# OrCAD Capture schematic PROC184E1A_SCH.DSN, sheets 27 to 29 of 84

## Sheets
27 26. SOC DIGITAL POWER 3: size C; title: SOC DIGITAL POWER 3; company: TEXAS INSTRUMENTS INCORPORATED; note: PROC184_SCH
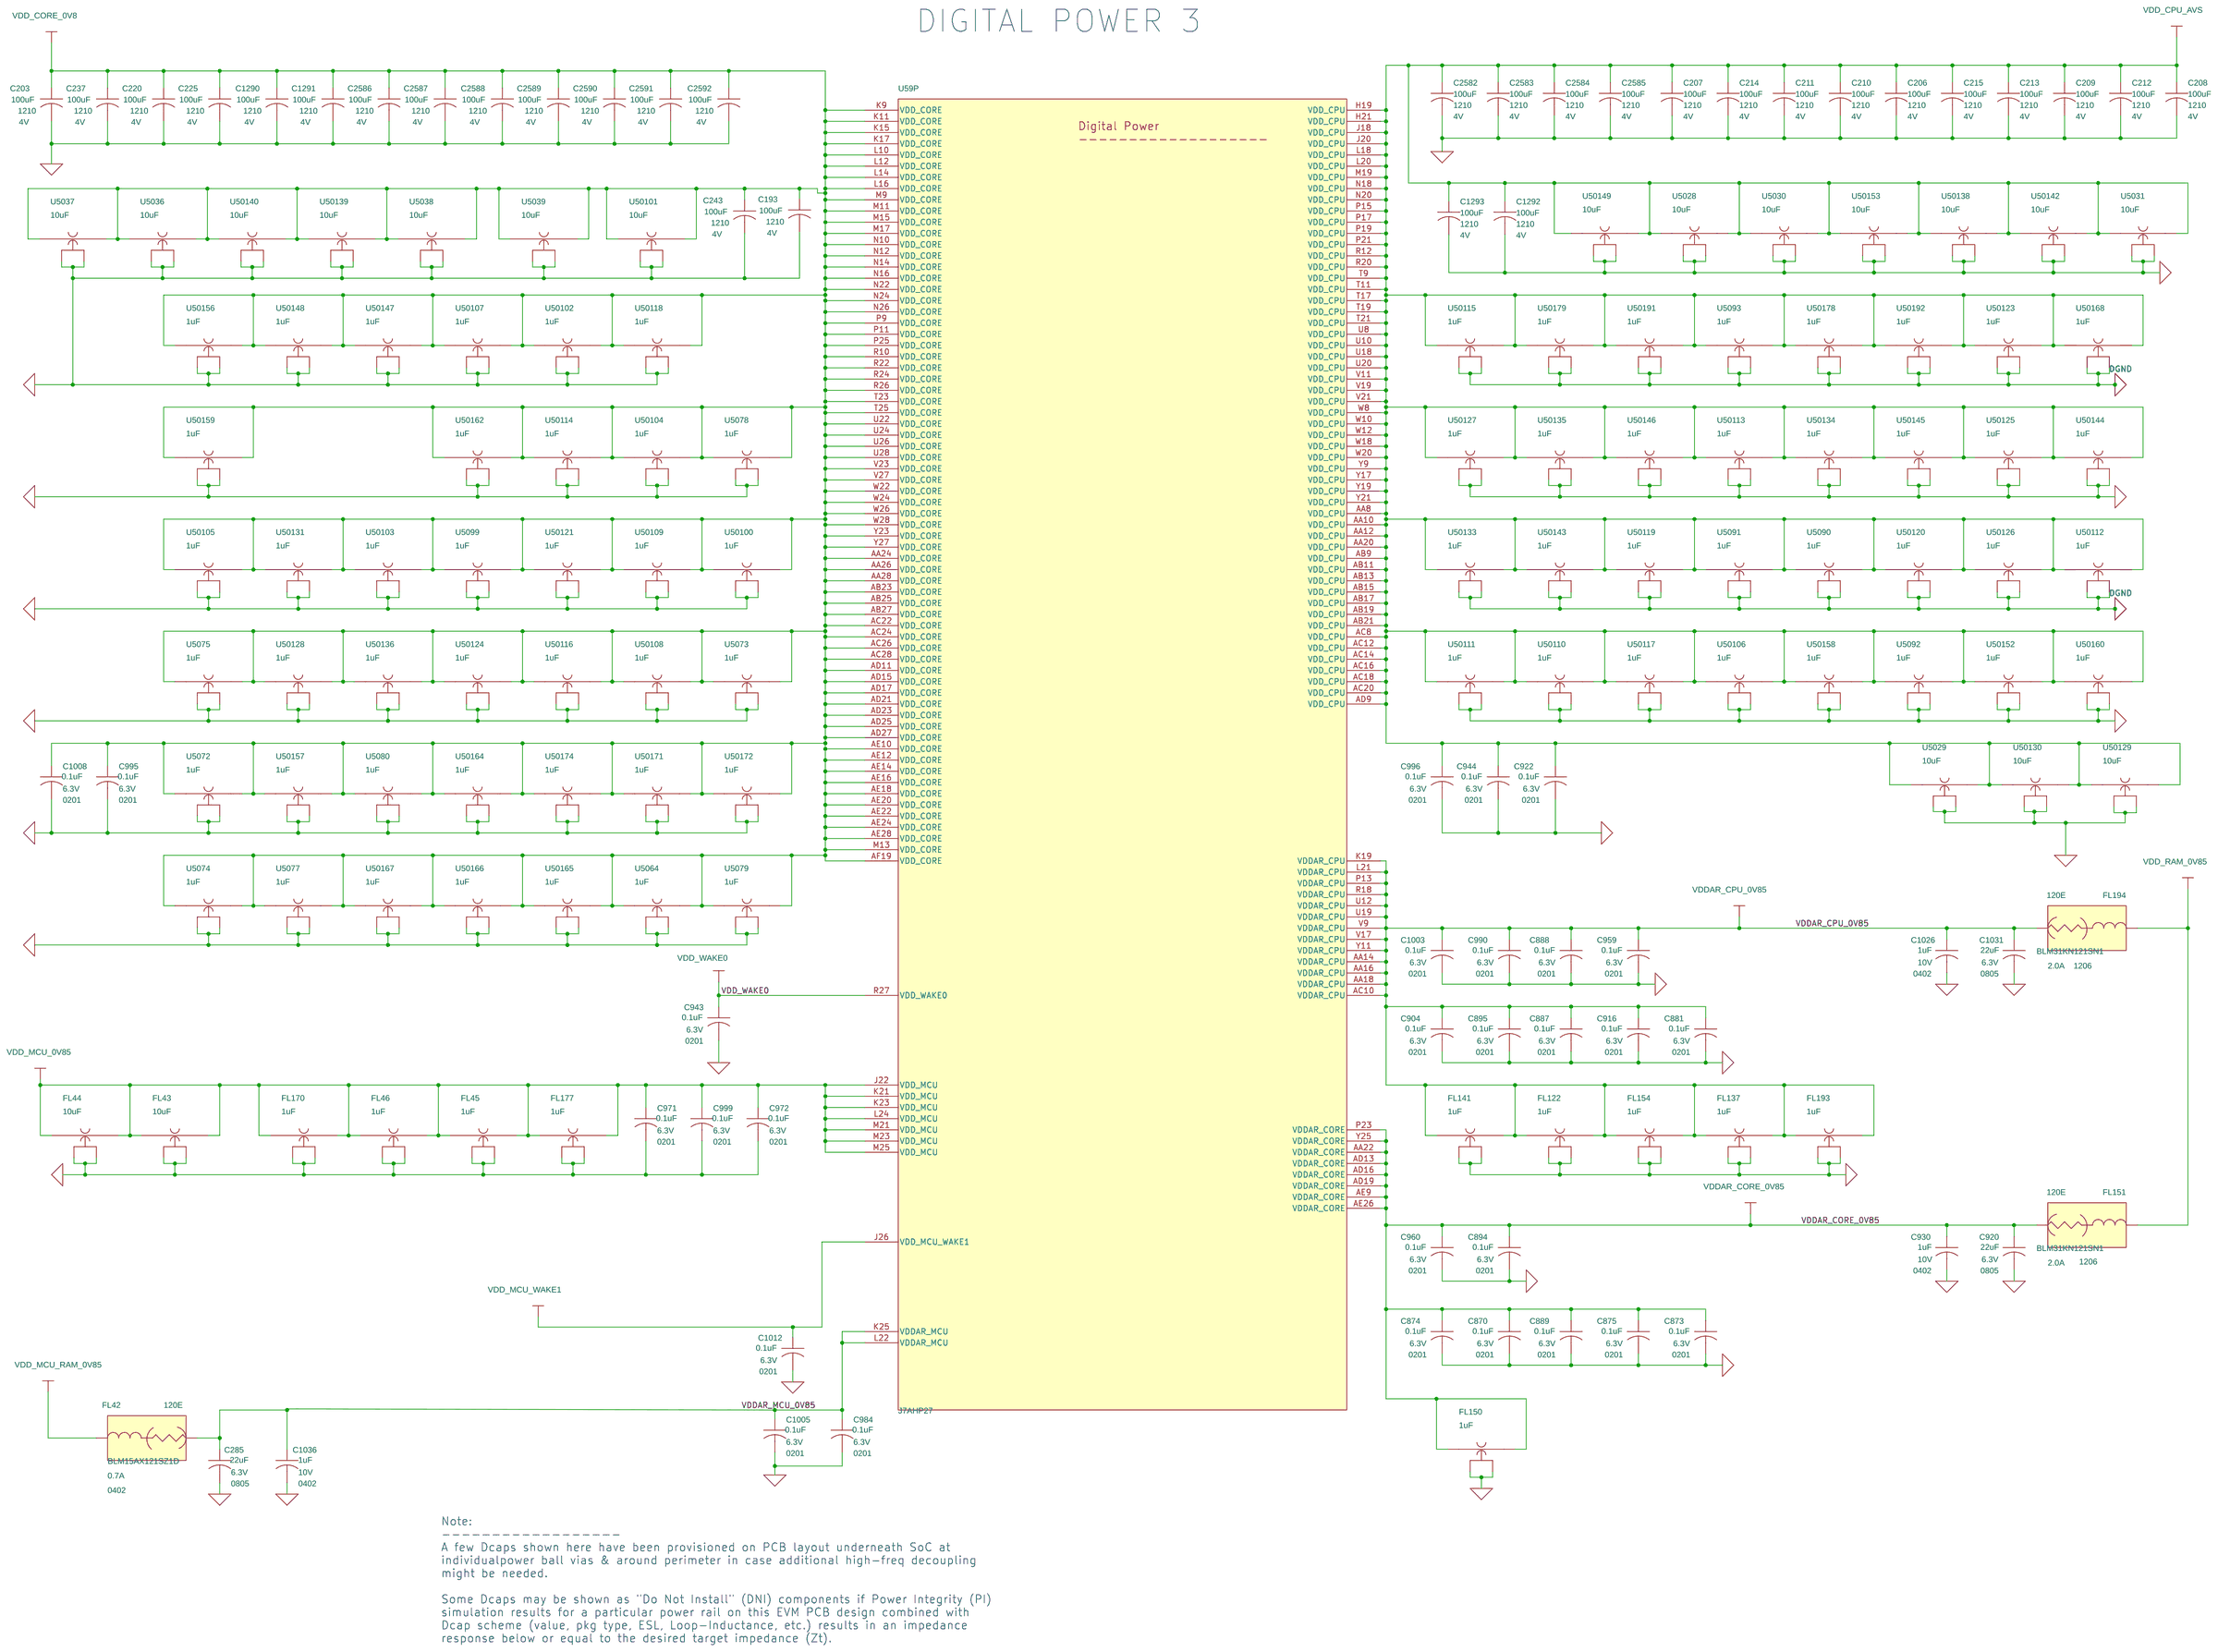
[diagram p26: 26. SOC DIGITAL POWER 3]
28 27. SOC GND & KELVIN SENSING: size C; title: SOC GROUND; company: TEXAS INSTRUMENTS INCORPORATED; note: PROC184_SCH
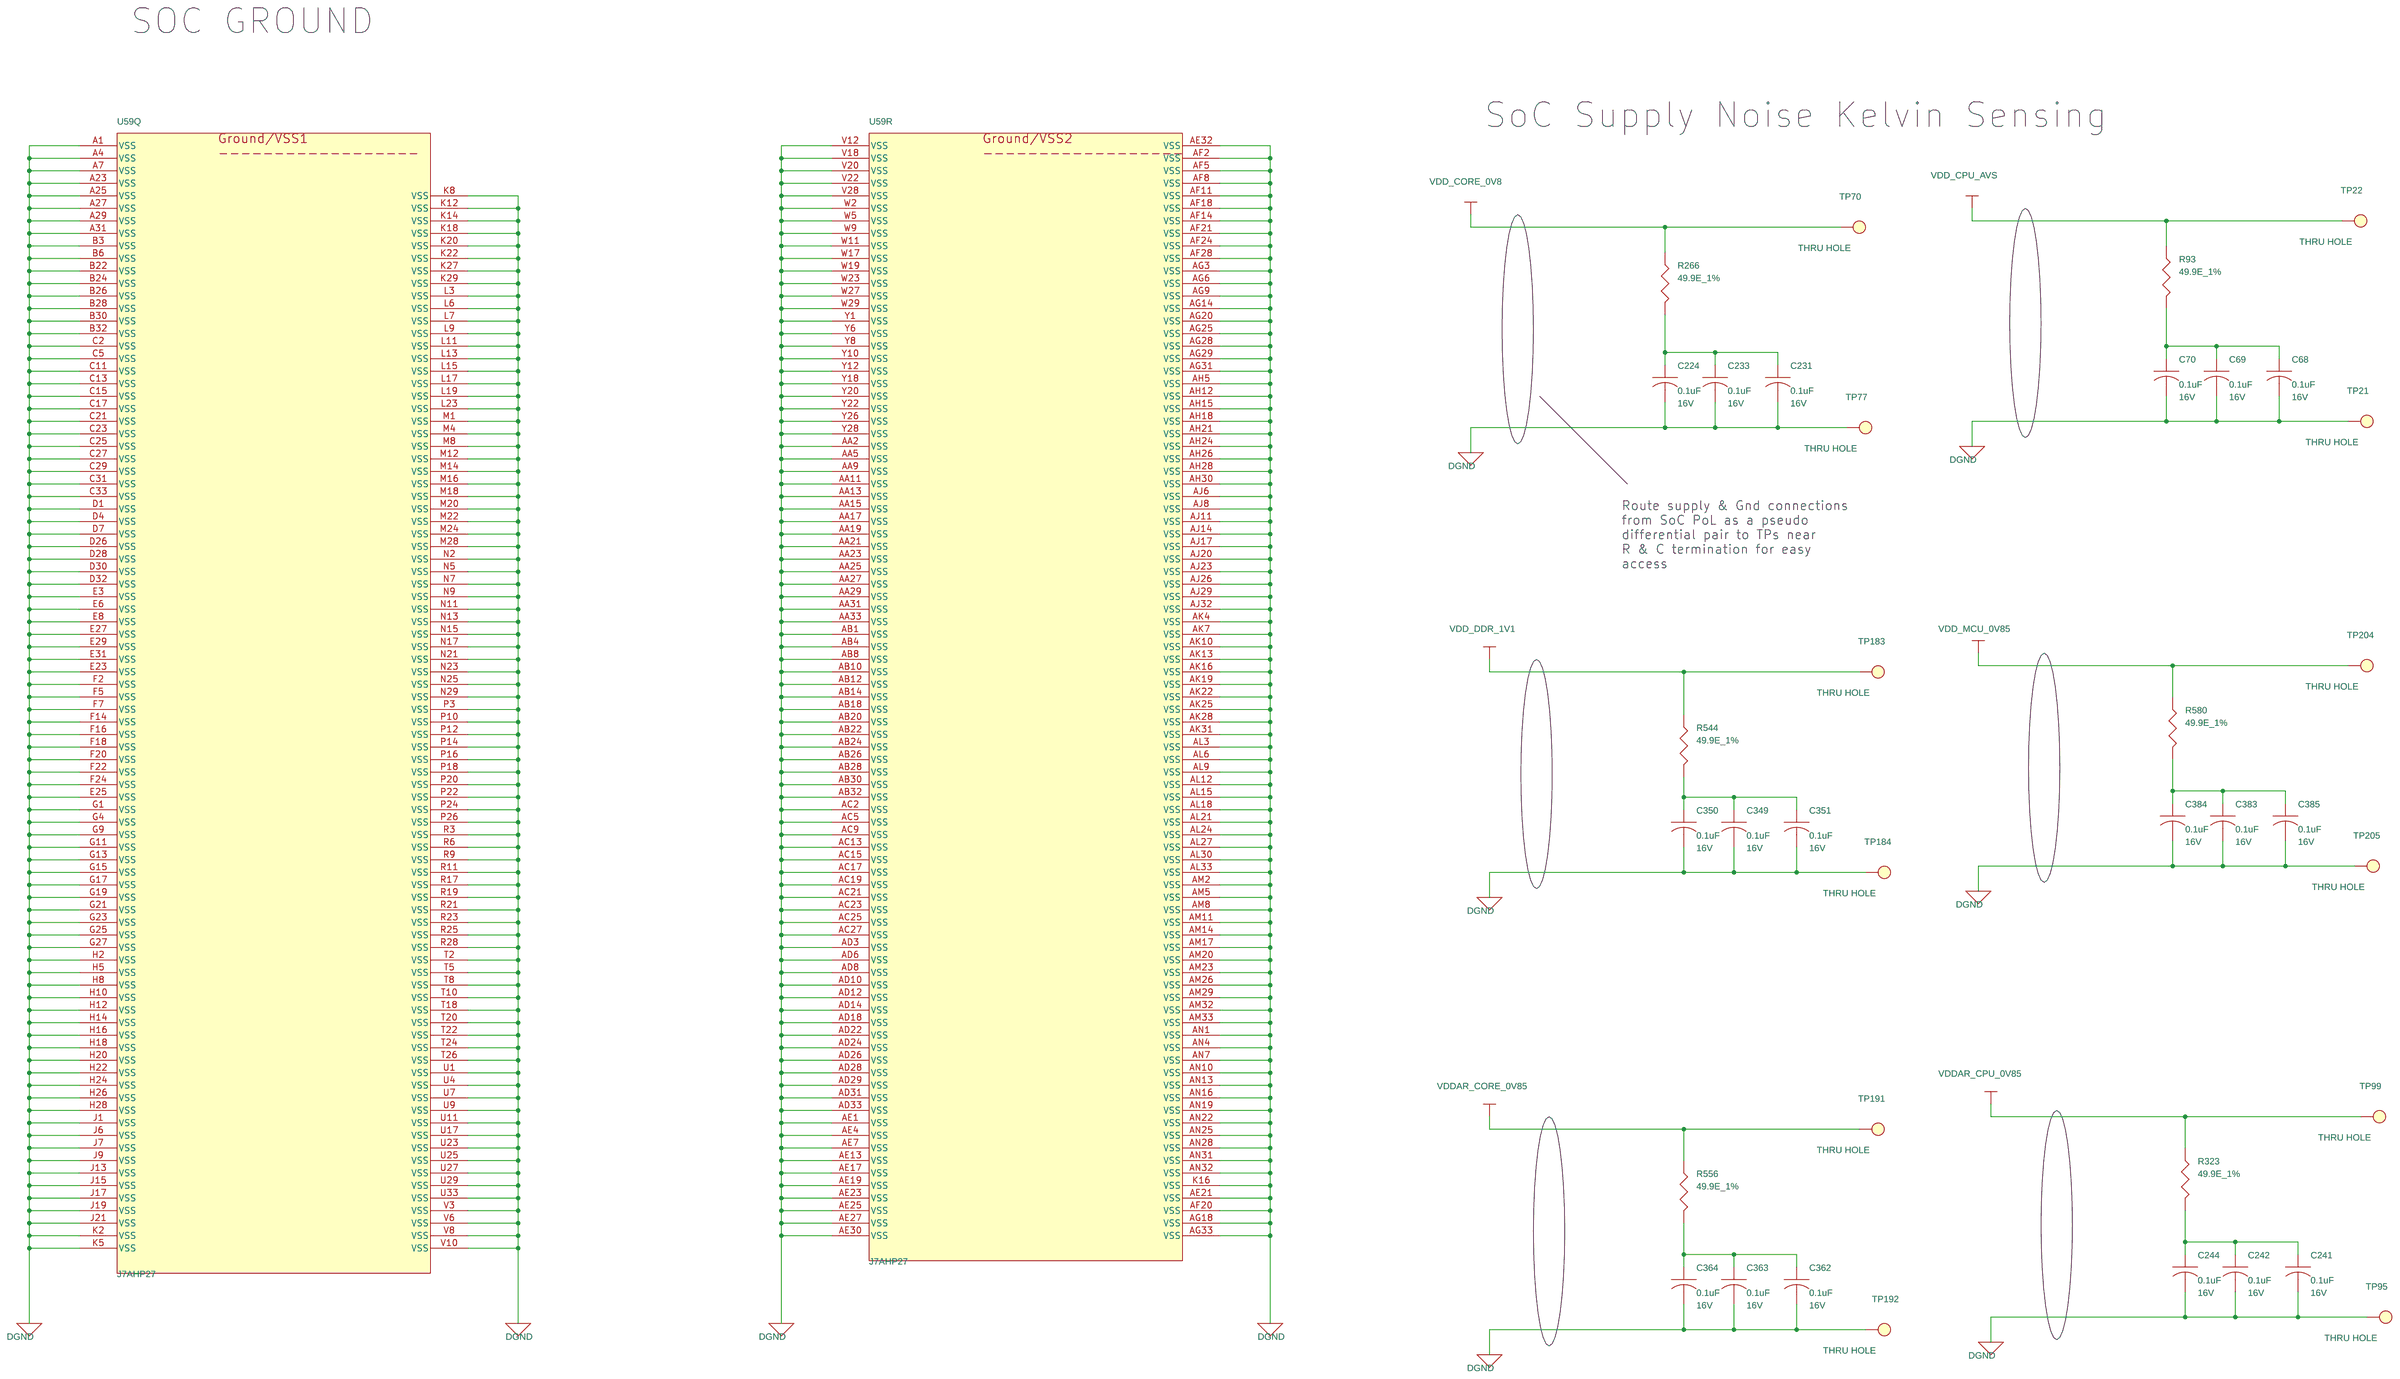
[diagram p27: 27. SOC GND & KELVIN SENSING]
29 33. EVM HYPERLINK & CSI TX CONN: size C; title: HYPERLINK & CSI TX CONNECTOR; company: TEXAS INSTRUMENTS INCORPORATED; note: PROC184_SCH
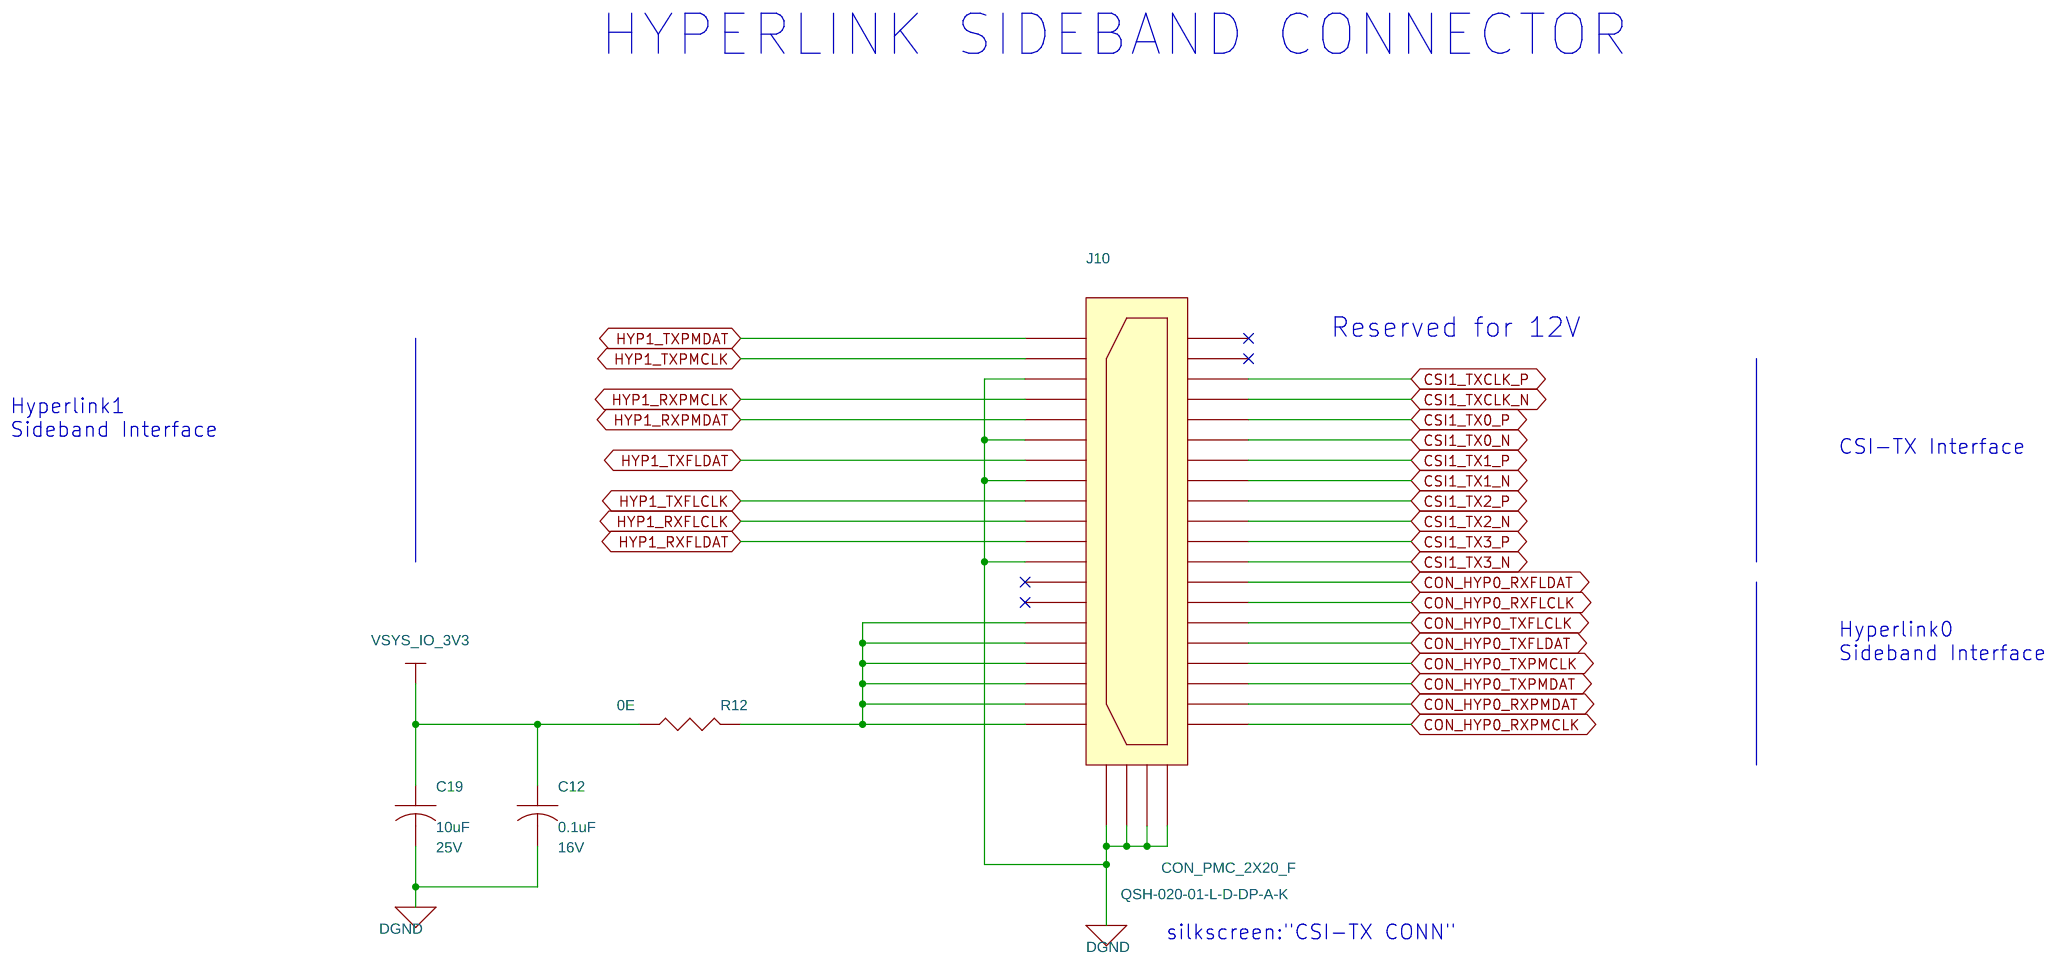
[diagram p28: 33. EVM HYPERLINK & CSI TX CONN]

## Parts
sheet 15. SOC EMIF1 & LPDDR4
U59  J7AHP27  [BGASKT-33X33-1063-P8MM]  (sections A,B,C,D,E,F,G,H,I,J,K,L,M,N,O,P,Q,R,S,T,U,V,W)
sheet 26. SOC DIGITAL POWER 3
C193  100uF  [CAP1210_3]
C203  100uF  [CAP1210_3]
C206  100uF  [CAP1210_3]
C207  100uF  [CAP1210_3]
C208  100uF  [CAP1210_3]
C209  100uF  [CAP1210_3]
C210  100uF  [CAP1210_3]
C211  100uF  [CAP1210_3]
C212  100uF  [CAP1210_3]
C213  100uF  [CAP1210_3]
C214  100uF  [CAP1210_3]
C215  100uF  [CAP1210_3]
C220  100uF  [CAP1210_3]
C225  100uF  [CAP1210_3]
C237  100uF  [CAP1210_3]
C243  100uF  [CAP1210_3]
C285  22uF  [CAP0805_1-25]
C870  0.1uF  [CAP0201_0-5]
C873  0.1uF  [CAP0201_0-5]
C874  0.1uF  [CAP0201_0-5]
C875  0.1uF  [CAP0201_0-5]
C881  0.1uF  [CAP0201_0-5]
C887  0.1uF  [CAP0201_0-5]
C888  0.1uF  [CAP0201_0-5]
C889  0.1uF  [CAP0201_0-5]
C894  0.1uF  [CAP0201_0-5]
C895  0.1uF  [CAP0201_0-5]
C904  0.1uF  [CAP0201_0-5]
C916  0.1uF  [CAP0201_0-5]
C920  22uF  [CAP0805_1-25]
C922  0.1uF  [CAP0201_0-5]
C930  1uF  [CAP0402_0-75]
C943  0.1uF  [CAP0201_0-5]
C944  0.1uF  [CAP0201_0-5]
C959  0.1uF  [CAP0201_0-5]
C960  0.1uF  [CAP0201_0-5]
C971  0.1uF  [CAP0201_0-5]
C972  0.1uF  [CAP0201_0-5]
C984  0.1uF  [CAP0201_0-5]
C990  0.1uF  [CAP0201_0-5]
C995  0.1uF  [CAP0201_0-5]
C996  0.1uF  [CAP0201_0-5]
C999  0.1uF  [CAP0201_0-5]
C1003  0.1uF  [CAP0201_0-5]
C1005  0.1uF  [CAP0201_0-5]
C1008  0.1uF  [CAP0201_0-5]
C1012  0.1uF  [CAP0201_0-5]
C1026  1uF  [CAP0402_0-75]
C1031  22uF  [CAP0805_1-25]
C1036  1uF  [CAP0402_0-75]
C1290  100uF  [CAP1210_3]
C1291  100uF  [CAP1210_3]
C1292  100uF  [CAP1210_3]
C1293  100uF  [CAP1210_3]
C2582  100uF  [CAP1210_3]
C2583  100uF  [CAP1210_3]
C2584  100uF  [CAP1210_3]
C2585  100uF  [CAP1210_3]
C2586  100uF  [CAP1210_3]
C2587  100uF  [CAP1210_3]
C2588  100uF  [CAP1210_3]
C2589  100uF  [CAP1210_3]
C2590  100uF  [CAP1210_3]
C2591  100uF  [CAP1210_3]
C2592  100uF  [CAP1210_3]
FL42  120E  [EMIFIL_BLM15A_0402_0-6]
FL43  10uF  [EMIFIL_NFM18C_0603_0-7_TI]
FL44  10uF  [EMIFIL_NFM18C_0603_0-7_TI]
FL45  1uF  [EMIFIL_NFM15CC_0402_0-5_TI]
FL46  1uF  [EMIFIL_NFM15CC_0402_0-5_TI]
FL122  1uF  [EMIFIL_NFM15CC_0402_0-5_TI]
FL137  1uF  [EMIFIL_NFM15CC_0402_0-5_TI]
FL141  1uF  [EMIFIL_NFM15CC_0402_0-5_TI]
FL150  1uF  [EMIFIL_NFM15CC_0402_0-5_TI]
FL151  120E  [EMIFIL_BLM31KN_1206_1-8]
FL154  1uF  [EMIFIL_NFM15CC_0402_0-5_TI]
FL170  1uF  [EMIFIL_NFM15CC_0402_0-5_TI]
FL177  1uF  [EMIFIL_NFM15CC_0402_0-5_TI]
FL193  1uF  [EMIFIL_NFM15CC_0402_0-5_TI]
FL194  120E  [EMIFIL_BLM31KN_1206_1-8]
U5028  10uF  [EMIFIL_NFM18C_0603_0-7_TI]
U5029  10uF  [EMIFIL_NFM18C_0603_0-7_TI]
U5030  10uF  [EMIFIL_NFM18C_0603_0-7_TI]
U5031  10uF  [EMIFIL_NFM18C_0603_0-7_TI]
U5036  10uF  [EMIFIL_NFM18C_0603_0-7_TI]
U5037  10uF  [EMIFIL_NFM18C_0603_0-7_TI]
U5038  10uF  [EMIFIL_NFM18C_0603_0-7_TI]
U5039  10uF  [EMIFIL_NFM18C_0603_0-7_TI]
U5064  1uF  [EMIFIL_NFM15CC_0402_0-5_TI]
U5072  1uF  [EMIFIL_NFM15CC_0402_0-5_TI]
U5073  1uF  [EMIFIL_NFM15CC_0402_0-5_TI]
U5074  1uF  [EMIFIL_NFM15CC_0402_0-5_TI]
U5075  1uF  [EMIFIL_NFM15CC_0402_0-5_TI]
U5077  1uF  [EMIFIL_NFM15CC_0402_0-5_TI]
U5078  1uF  [EMIFIL_NFM15CC_0402_0-5_TI]
U5079  1uF  [EMIFIL_NFM15CC_0402_0-5_TI]
U5080  1uF  [EMIFIL_NFM15CC_0402_0-5_TI]
U5090  1uF  [EMIFIL_NFM15CC_0402_0-5_TI]
U5091  1uF  [EMIFIL_NFM15CC_0402_0-5_TI]
U5092  1uF  [EMIFIL_NFM15CC_0402_0-5_TI]
U5093  1uF  [EMIFIL_NFM15CC_0402_0-5_TI]
U5099  1uF  [EMIFIL_NFM15CC_0402_0-5_TI]
U50100  1uF  [EMIFIL_NFM15CC_0402_0-5_TI]
U50101  10uF  [EMIFIL_NFM18C_0603_0-7_TI]
U50102  1uF  [EMIFIL_NFM15CC_0402_0-5_TI]
U50103  1uF  [EMIFIL_NFM15CC_0402_0-5_TI]
U50104  1uF  [EMIFIL_NFM15CC_0402_0-5_TI]
U50105  1uF  [EMIFIL_NFM15CC_0402_0-5_TI]
U50106  1uF  [EMIFIL_NFM15CC_0402_0-5_TI]
U50107  1uF  [EMIFIL_NFM15CC_0402_0-5_TI]
U50108  1uF  [EMIFIL_NFM15CC_0402_0-5_TI]
U50109  1uF  [EMIFIL_NFM15CC_0402_0-5_TI]
U50110  1uF  [EMIFIL_NFM15CC_0402_0-5_TI]
U50111  1uF  [EMIFIL_NFM15CC_0402_0-5_TI]
U50112  1uF  [EMIFIL_NFM15CC_0402_0-5_TI]
U50113  1uF  [EMIFIL_NFM15CC_0402_0-5_TI]
U50114  1uF  [EMIFIL_NFM15CC_0402_0-5_TI]
U50115  1uF  [EMIFIL_NFM15CC_0402_0-5_TI]
U50116  1uF  [EMIFIL_NFM15CC_0402_0-5_TI]
U50117  1uF  [EMIFIL_NFM15CC_0402_0-5_TI]
U50118  1uF  [EMIFIL_NFM15CC_0402_0-5_TI]
U50119  1uF  [EMIFIL_NFM15CC_0402_0-5_TI]
U50120  1uF  [EMIFIL_NFM15CC_0402_0-5_TI]
U50121  1uF  [EMIFIL_NFM15CC_0402_0-5_TI]
U50123  1uF  [EMIFIL_NFM15CC_0402_0-5_TI]
U50124  1uF  [EMIFIL_NFM15CC_0402_0-5_TI]
U50125  1uF  [EMIFIL_NFM15CC_0402_0-5_TI]
U50126  1uF  [EMIFIL_NFM15CC_0402_0-5_TI]
U50127  1uF  [EMIFIL_NFM15CC_0402_0-5_TI]
U50128  1uF  [EMIFIL_NFM15CC_0402_0-5_TI]
U50129  10uF  [EMIFIL_NFM18C_0603_0-7_TI]
U50130  10uF  [EMIFIL_NFM18C_0603_0-7_TI]
U50131  1uF  [EMIFIL_NFM15CC_0402_0-5_TI]
U50133  1uF  [EMIFIL_NFM15CC_0402_0-5_TI]
U50134  1uF  [EMIFIL_NFM15CC_0402_0-5_TI]
U50135  1uF  [EMIFIL_NFM15CC_0402_0-5_TI]
U50136  1uF  [EMIFIL_NFM15CC_0402_0-5_TI]
U50138  10uF  [EMIFIL_NFM18C_0603_0-7_TI]
U50139  10uF  [EMIFIL_NFM18C_0603_0-7_TI]
U50140  10uF  [EMIFIL_NFM18C_0603_0-7_TI]
U50142  10uF  [EMIFIL_NFM18C_0603_0-7_TI]
U50143  1uF  [EMIFIL_NFM15CC_0402_0-5_TI]
U50144  1uF  [EMIFIL_NFM15CC_0402_0-5_TI]
U50145  1uF  [EMIFIL_NFM15CC_0402_0-5_TI]
U50146  1uF  [EMIFIL_NFM15CC_0402_0-5_TI]
U50147  1uF  [EMIFIL_NFM15CC_0402_0-5_TI]
U50148  1uF  [EMIFIL_NFM15CC_0402_0-5_TI]
U50149  10uF  [EMIFIL_NFM18C_0603_0-7_TI]
U50152  1uF  [EMIFIL_NFM15CC_0402_0-5_TI]
U50153  10uF  [EMIFIL_NFM18C_0603_0-7_TI]
U50156  1uF  [EMIFIL_NFM15CC_0402_0-5_TI]
U50157  1uF  [EMIFIL_NFM15CC_0402_0-5_TI]
U50158  1uF  [EMIFIL_NFM15CC_0402_0-5_TI]
U50159  1uF  [EMIFIL_NFM15CC_0402_0-5_TI]
U50160  1uF  [EMIFIL_NFM15CC_0402_0-5_TI]
U50162  1uF  [EMIFIL_NFM15CC_0402_0-5_TI]
U50164  1uF  [EMIFIL_NFM15CC_0402_0-5_TI]
U50165  1uF  [EMIFIL_NFM15CC_0402_0-5_TI]
U50166  1uF  [EMIFIL_NFM15CC_0402_0-5_TI]
U50167  1uF  [EMIFIL_NFM15CC_0402_0-5_TI]
U50168  1uF  [EMIFIL_NFM15CC_0402_0-5_TI]
U50171  1uF  [EMIFIL_NFM15CC_0402_0-5_TI]
U50172  1uF  [EMIFIL_NFM15CC_0402_0-5_TI]
U50174  1uF  [EMIFIL_NFM15CC_0402_0-5_TI]
U50178  1uF  [EMIFIL_NFM15CC_0402_0-5_TI]
U50179  1uF  [EMIFIL_NFM15CC_0402_0-5_TI]
U50191  1uF  [EMIFIL_NFM15CC_0402_0-5_TI]
U50192  1uF  [EMIFIL_NFM15CC_0402_0-5_TI]
sheet 27. SOC GND & KELVIN SENSING
C68  0.1uF  [CAP0402_0-75]
C69  0.1uF  [CAP0402_0-75]
C70  0.1uF  [CAP0402_0-75]
C224  0.1uF  [CAP0402_0-75]
C231  0.1uF  [CAP0402_0-75]
C233  0.1uF  [CAP0402_0-75]
C241  0.1uF  [CAP0402_0-75]
C242  0.1uF  [CAP0402_0-75]
C244  0.1uF  [CAP0402_0-75]
C349  0.1uF  [CAP0402_0-75]
C350  0.1uF  [CAP0402_0-75]
C351  0.1uF  [CAP0402_0-75]
C362  0.1uF  [CAP0402_0-75]
C363  0.1uF  [CAP0402_0-75]
C364  0.1uF  [CAP0402_0-75]
C383  0.1uF  [CAP0402_0-75]
C384  0.1uF  [CAP0402_0-75]
C385  0.1uF  [CAP0402_0-75]
R93  49.9E_1%  [RES0402_0-5]
R266  49.9E_1%  [RES0402_0-5]
R323  49.9E_1%  [RES0402_0-5]
R544  49.9E_1%  [RES0402_0-5]
R556  49.9E_1%  [RES0402_0-5]
R580  49.9E_1%  [RES0402_0-5]
TP21  THRU HOLE  [TP_40X65]
TP22  THRU HOLE  [TP_40X65]
TP70  THRU HOLE  [TP_40X65]
TP77  THRU HOLE  [TP_40X65]
TP95  THRU HOLE  [TP_40X65]
TP99  THRU HOLE  [TP_40X65]
TP183  THRU HOLE  [TP_40X65]
TP184  THRU HOLE  [TP_40X65]
TP191  THRU HOLE  [TP_40X65]
TP192  THRU HOLE  [TP_40X65]
TP204  THRU HOLE  [TP_40X65]
TP205  THRU HOLE  [TP_40X65]
sheet 33. EVM HYPERLINK & CSI TX CONN
C12  0.1uF  [CAP0402_0-75]
C19  10uF  [CAP0603_1-25]
J10  CON_PMC_2X20_F  [CON_PMC2X20_QSH-020-01-D-DP-A_S_S_S_3-4]
R12  0E  [RES0402_0-5]

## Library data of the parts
U59 = J7AHP27SoC_BGA1063: IC J7AHP27 SoC EVM MICROPROCESSOR BGA1063; Chkd/date: PRADEEP/181223; Crtd /date: TAMILARASU/111223; Custom_Duty: 15%; Customs_HS_Code: 85423100; Distributor_name: NA; Distributor_part_number: NA; Footprint Path: Y:\MIS_DATABASE\Library\ALTIUM_TOOL\PCB_FOOTPRINTS\Altium_Footprint_Lib.PcbLib; Height: 3.30MM; Library Path: Y:\MIS_DATABASE\Library\ALTIUM_TOOL\SCHEMATICS_PARTS\MS_MICROPROCESSOR_Library.schlib; Mfr_name: NA; Mistral Part No: 141223120002; Package: BGA1063; Part_type: ICS\DIGITAL\MICROPROCESSOR; Project: J7AHP27_V08 SOC; RoHS: NA; Temperature: NA; Tolerance: NA; Voltage: NA; Wattage: NA; Weight: NA; Datasheet: Y:\MIS_DATABASE\DATASHEETS\ICS\DIGITAL\MICROCONTROLLER\J7AHP27.PDF
C193 C203 C206-C215 C220 C225 C237 C243 C1290-C1293 C2582-C2592 = CAP: CAP CERAMIC 100uF 4V 20% X7R 1210; Automotive Alternate_mfr_name: TDK; Automotive Alternate_mfr_part_number: CGA6P1X7S1A476M; Chkd/date: PRAVEEN/080922; Crtd /date: PRAVEEN/080922; Custom_Duty: 15%; Customs_HS_Code: 85322990; Direct Alternate_mfr_name: TDK; Direct Alternate_mfr_part_number: CGA6P1X7S1A476M; Distributor_name: NA; Distributor_part_number: NA; Footprint Path: Y:\MIS_DATABASE\Library\ALTIUM_TOOL\PCB_FOOTPRINTS\Altium_Footprint_Lib.PcbLib; Height: 2.85MM; Library Path: Y:\MIS_DATABASE\Library\ALTIUM_TOOL\SCHEMATICS_PARTS\MS_DISCRETE_Library.schlib; Manufacturer: MURATA; Mfr_name: MURATA; Mfr_part_number: GCM32ED70G107MEC4; Mistral Part No: 120022090010-R; Package: 1210; Part_type: CAPACITORS\CERAMIC; Project: J7ES_EVM_FUSION2_BRD; RoHS: RoHS; Temperature: NA; Tolerance: 20%; Voltage: 4V; Wattage: NA; Weight: NA; Datasheet: Y:\MIS_DATABASE\DATASHEETS\CAPACITORS\GCM32ED70G107MEC4.PDF
C285 C920 C1031 = CAP: CAP CERAMIC 22uF 6.3V 20% X7T AUTO 0805; Automotive Alternate_mfr_name: TDK; Automotive Alternate_mfr_part_number: CGA4J1X7T0J226M; Chkd/date: MANIRAJA/261018; Crtd /date: ALVY/251018; Custom_Duty: 15%; Customs_HS_Code: 85322990; Distributor_name: MOUSER; Distributor_part_number: 81-GCM21BD70J226ME6L; Footprint Path: Y:\MIS_DATABASE\Library\ALTIUM_TOOL\PCB_FOOTPRINTS\Altium_Footprint_Lib.PcbLib; Height: 1.25MM; Library Path: Y:\MIS_DATABASE\Library\ALTIUM_TOOL\SCHEMATICS_PARTS\MS_DISCRETE_Library.schlib; Manufacturer: MURATA; Mfr_name: MURATA; Mfr_part_number: GCM21BD70J226ME36L; Mistral Part No: 120018100065-R; Package: 0805; Part_type: CAPACITORS\CERAMIC; Project: TI_J7ES_EVM_SOM; RoHS: RoHS; Temperature: -55°C+125°C; Tolerance: 20%; Voltage: 6.3V; Wattage: NA; Weight: NA; Datasheet: Y:\MIS_DATABASE\DATASHEETS\CAPACITORS\GCM-SERIES.PDF
C870 C873 C875 C881 C894 C895 C916 C922 C943 C944 C959 C971 C990 C999 C1005 C1008 C1012 = CAP: CAP CERAMIC 0.1uF 6.3V 10% X7S AUTO 0201; Chkd/date: MANIRAJA/011018; Crtd /date: MANIRAJA/011018; Custom_Duty: 15%; Customs_HS_Code: 85322990; Distributor_name: NA; Distributor_part_number: NA; Footprint Path: Y:\MIS_DATABASE\Library\ALTIUM_TOOL\PCB_FOOTPRINTS\Altium_Footprint_Lib.PcbLib; Height: 0.33MM; Library Path: Y:\MIS_DATABASE\Library\ALTIUM_TOOL\SCHEMATICS_PARTS\MS_DISCRETE_Library.schlib; Manufacturer: MURATA; Mfr_name: MURATA; Mfr_part_number: GCM033C70J104KE02D; Mistral Part No: 120018100001-R; Package: 0201; Part_type: CAPACITORS\CERAMIC; Project: TI_J7_SVB-DUT; RoHS: RoHS; Temperature: -55°C+125°C; Tolerance: 10%; Voltage: 6.3V; Wattage: NA; Weight: NA; Datasheet: Y:\MIS_DATABASE\DATASHEETS\CAPACITORS\MURATA-GCM-SER.PDF
C874 C887-C889 C904 C960 C972 C984 C995 C996 C1003 = CAP: CAP CERAMIC 0.1uF 6.3V 10% X7S AUTO 0201; Assembly_Instruction: DNI; Chkd/date: MANIRAJA/011018; Crtd /date: MANIRAJA/011018; Custom_Duty: 15%; Customs_HS_Code: 85322990; Distributor_name: NA; Distributor_part_number: NA; Footprint Path: Y:\MIS_DATABASE\Library\ALTIUM_TOOL\PCB_FOOTPRINTS\Altium_Footprint_Lib.PcbLib; Height: 0.33MM; Library Path: Y:\MIS_DATABASE\Library\ALTIUM_TOOL\SCHEMATICS_PARTS\MS_DISCRETE_Library.schlib; Manufacturer: MURATA; Mfr_name: MURATA; Mfr_part_number: GCM033C70J104KE02D; Mistral Part No: 120018100001-R; Package: 0201; Part_type: CAPACITORS\CERAMIC; Project: TI_J7_SVB-DUT; RoHS: RoHS; Temperature: -55°C+125°C; Tolerance: 10%; Voltage: 6.3V; Wattage: NA; Weight: NA; Datasheet: Y:\MIS_DATABASE\DATASHEETS\CAPACITORS\MURATA-GCM-SER.PDF
C930 C1026 C1036 = CAP: CAP CERAMIC 1uF 10V 10% X7S AUTO 0402; Chkd/date: MANIRAJA/100918; Crtd /date: ALVY/100918; Custom_Duty: 15%; Customs_HS_Code: 85322990; Distributor_name: DIGIKEY; Distributor_part_number: 490-13409-1-ND; Footprint Path: Y:\MIS_DATABASE\Library\ALTIUM_TOOL\PCB_FOOTPRINTS\Altium_Footprint_Lib.PcbLib; Height: 0.70MM; Library Path: Y:\MIS_DATABASE\Library\ALTIUM_TOOL\SCHEMATICS_PARTS\MS_DISCRETE_Library.schlib; Manufacturer: MURATA; Mfr_name: MURATA; Mfr_part_number: GCM155C71A105KE38D; Mistral Part No: 120018090021-R; Package: 0402; Part_type: CAPACITORS\CERAMIC; Project: SMART-M_SCRIPTALK_PB; RoHS: RoHS; Temperature: -55°C+125°C; Tolerance: 10%; Voltage: 10V; Wattage: NA; Weight: 6mg; Datasheet: Y:\MIS_DATABASE\DATASHEETS\CAPACITORS\MURATA-GCM-SER.PDF
FL42 = EMIFILTER_IND: IND FERRITE BEAD CHIP 120E 700mA 0402; Automotive Alternate_mfr_name: TDK; Automotive Alternate_mfr_part_number: MPZ1608S121ATDH5; Chkd/date: MANIRAJA/170122; Crtd /date: TAMILARASU/170122; Custom_Duty: 24%; Customs_HS_Code: 85437099; Direct Alternate_mfr_name: TDK; Direct Alternate_mfr_part_number: MPZ1608S121ATAH0; Distributor_name: DIGIKEY; Distributor_part_number: 490-16510-1-ND; Footprint Path: Y:\MIS_DATABASE\Library\ALTIUM_TOOL\PCB_FOOTPRINTS\Altium_Footprint_Lib.PcbLib; Height: 0.55MM; Library Path: Y:\MIS_DATABASE\Library\ALTIUM_TOOL\SCHEMATICS_PARTS\MS_FILTER_Library.schlib; Manufacturer: MURATA; Mfr_name: MURATA; Mfr_part_number: BLM15AX121SZ1D; Mistral Part No: 130022010017-R; Package: 0402; Part_type: INDUCTOR; Project: J7AHP_PROTO_BRD; RoHS: RoHS; SAT Current: 0.7A; Temperature: -55°C+125°C; Tolerance: 25%; Voltage: NA; Wattage: NA; Weight: 1mg; Datasheet: Y:\MIS_DATABASE\DATASHEETS\DISCRETES\INDUCTORS\BLM15-SZ1D-SER.PDF
FL43 FL44 U5028-U5031 U5036-U5039 U50101 U50129 U50130 U50138-U50140 U50142 U50149 U50153 = CAP_NFM_TI: PASSIVE FILTER EMI 10uF 4V AUTO 0603; Chkd/date: MANIRAJA/251018; Crtd /date: ALVY/251018; Custom_Duty: 15%; Customs_HS_Code: 85412900; Distributor_name: NA; Distributor_part_number: NA; Footprint Path: Y:\MIS_DATABASE\Library\ALTIUM_TOOL\PCB_FOOTPRINTS\Altium_Footprint_Lib.PcbLib; Height: 0.70MM; Library Path: Y:\MIS_DATABASE\Library\ALTIUM_TOOL\SCHEMATICS_PARTS\MS_FILTER_Library.schlib; Mfr_name: MURATA; Mfr_part_number: NFM18HC106D0G_TI; Mistral Part No: 130018100049; Package: 0603; Part_type: FILTER; Project: TI_J7ES_EVM_SOM; RoHS: NA; Temperature: NA; Tolerance: NA; Voltage: 4V; Wattage: NA; Weight: NA; Datasheet: Y:\MIS_DATABASE\DATASHEETS\DISCRETES\INDUCTORS\NFM18HC-SER.PDF
FL45 FL46 FL122 FL137 FL141 FL150 FL154 FL170 FL177 FL193 U5064 U5072-U5075 U5077-U5080 U5090-U5093 U5099 U50100 U50102-U50121 U50123-U50128 U50131 U50133-U50136 U50143-U50148 U50152 U50156-U50160 U50162 U50164-U50168 U50171 U50172 U50174 U50178 U50179 U50191 U50192 = CAP_NFM_TI: PASSIVE FILTER EMI 1uF 4V AUTO 0402; Chkd/date: MANIRAJA/251018; Crtd /date: ALVY/251018; Custom_Duty: 15%; Customs_HS_Code: 85412900; Distributor_name: NA; Distributor_part_number: NA; Footprint Path: Y:\MIS_DATABASE\Library\ALTIUM_TOOL\PCB_FOOTPRINTS\Altium_Footprint_Lib.PcbLib; Height: 0.50MM; Library Path: Y:\MIS_DATABASE\Library\ALTIUM_TOOL\SCHEMATICS_PARTS\MS_FILTER_Library.schlib; Mfr_name: MURATA; Mfr_part_number: NFM15HC105D0G_TI; Mistral Part No: 130018100050; Package: 0402; Part_type: FILTER; Project: TI_J7ES_EVM_SOM; RoHS: NA; Temperature: NA; Tolerance: NA; Voltage: 4V; Wattage: NA; Weight: NA; Datasheet: Y:\MIS_DATABASE\DATASHEETS\DISCRETES\INDUCTORS\NFM15CC223C1A3.PDF
FL151 FL194 = EMIFILTER_IND: IND FERRITE BEAD CHIP 120E 6A 1206; Automotive Alternate_mfr_name: TDK; Automotive Alternate_mfr_part_number: MPZ1608S121ATDH5; Chkd/date: PRAVEEN/140922; Crtd /date: PRAVEEN/140922; Custom_Duty: 24%; Customs_HS_Code: 85437099; Direct Alternate_mfr_name: TDK; Direct Alternate_mfr_part_number: MPZ1608S121ATAH0; Distributor_name: DIGIKEY; Distributor_part_number: 490-16524-1-ND; Footprint Path: Y:\MIS_DATABASE\Library\ALTIUM_TOOL\PCB_FOOTPRINTS\Altium_Footprint_Lib.PcbLib; Height: 1.80MM; Library Path: Y:\MIS_DATABASE\Library\ALTIUM_TOOL\SCHEMATICS_PARTS\MS_FILTER_Library.schlib; Manufacturer: MURATA; Mfr_name: MURATA; Mfr_part_number: BLM31KN121SN1; Mistral Part No: 130022090033-R; Package: 1206; Part_type: INDUCTOR; Project: J7AHP_EVM; RoHS: RoHS; SAT Current: 2.0A; Temperature: -55°C+125°C; Tolerance: NA; Voltage: NA; Wattage: NA; Weight: 41mg; Datasheet: Y:\MIS_DATABASE\DATASHEETS\DISCRETES\INDUCTORS\BLM31KNXXXSH1L.PDF
C68-C70 C224 C231 C233 C241 C242 C244 C349-C351 C362-C364 C383-C385 = CAP: CAP CERAMIC 0.1uF 16V 10% X7R AUTO 0402; Automotive Alternate_mfr_name: TDK; Automotive Alternate_mfr_part_number: CGA2B1X7R1C104K050BC; Chkd/date: NAVEED/021014; Crtd /date: VASANTHA/300514; Custom_Duty: 15%; Customs_HS_Code: 85322990; Direct Alternate_mfr_name: TDK; Direct Alternate_mfr_part_number: CGA2B1X7R1C104K050BC; Distributor_name: DIGIKEY; Distributor_part_number: 490-4759-1-ND; Footprint Path: Y:\MIS_DATABASE\Library\ALTIUM_TOOL\PCB_FOOTPRINTS\Altium_Footprint_Lib.PcbLib; Height: 0.55MM; Library Path: Y:\MIS_DATABASE\Library\ALTIUM_TOOL\SCHEMATICS_PARTS\MS_DISCRETE_Library.schlib; Manufacturer: MURATA; Mfr_name: MURATA; Mfr_part_number: GCM155R71C104KA55D; Mistral Part No: 120016070006-R; Package: 0402; Part_type: CAPACITORS\CERAMIC; Project: DCMIST_FPGA_CARD; RoHS: RoHS; Temperature: -55°C+125°C; Tolerance: 10%; Voltage: 16V; Wattage: NA; Weight: 6mg; Datasheet: Y:\MIS_DATABASE\DATASHEETS\CAPACITORS\MURATA-GCM-SER.PDF
R93 R266 R323 R544 R556 R580 = RESISTOR: RES 49.9E 1/10W 1% 0402; Chkd/date: VASANTHA/201216; Crtd /date: MAZHAR/201005; Custom_Duty: 15%; Customs_HS_Code: 85332119; Distributor_name: DIGIKEY; Distributor_part_number: P49.9LCT-ND; Footprint Path: Y:\MIS_DATABASE\Library\ALTIUM_TOOL\PCB_FOOTPRINTS\Altium_Footprint_Lib.PcbLib; Height: 0.40MM; Library Path: Y:\MIS_DATABASE\Library\ALTIUM_TOOL\SCHEMATICS_PARTS\MS_DISCRETE_Library.schlib; Manufacturer: PANASONIC-ECG; Mfr_name: PANASONIC-ECG; Mfr_part_number: ERJ-2RKF49R9X; Mistral Part No: 110009030897-R; Package: 0402; Part_type: RESISTORS\FIXED; Project: RED EYE; RoHS: RoHS; Temperature: -55°C+155°C; Tolerance: 1%; Voltage: NA; Wattage: 1/10W; Weight: 0.8mg; Datasheet: Y:\MIS_DATABASE\DATASHEETS\RESISTORS\PAN-ERJSER_NOV17.PDF
TP21 TP22 TP70 TP77 TP95 TP99 TP183 TP184 TP191 TP192 TP204 TP205 = TESTPOINT: TESTPOINT 1.0MM DRILL PTH; Chkd/date: MAZHAR/271211; Crtd /date: SHREESHAIL/041005; Distributor_name: NA; Distributor_part_number: NA; Height: NA; Manufacturer: LOCAL; Mfr_name: LOCAL; Mistral Part No: 130009030938; Package: THRU-HOLE; Project: HSE; Datasheet: NA
C12 = CAP: CAP CERAMIC 0.1uF 16V 10% X7R AUTO 0402; Automotive Alternate_mfr_name: TDK; Automotive Alternate_mfr_part_number: CGA2B1X7R1C104K050BC; Chkd/date: NAVEED/021014; Crtd /date: VASANTHA/300514; Custom_Duty: 15%; Customs_HS_Code: 85322990; Direct Alternate_mfr_name: MURATA; Direct Alternate_mfr_part_number: GCM155R71C104JA55D; Distributor_name: DIGIKEY; Distributor_part_number: 490-4759-1-ND; Footprint Path: Y:\MIS_DATABASE\Library\ALTIUM_TOOL\PCB_FOOTPRINTS\Altium_Footprint_Lib.PcbLib; Height: 0.55MM; Library Path: Y:\MIS_DATABASE\Library\ALTIUM_TOOL\SCHEMATICS_PARTS\MS_DISCRETE_Library.schlib; Manufacturer: MURATA; Mfr_name: MURATA; Mfr_part_number: GCM155R71C104KA55D; Mistral Part No: 120016070006-R; Package: 0402; Part_type: CAPACITORS\CERAMIC; Project: DCMIST_FPGA_CARD; RoHS: RoHS; Temperature: -55°C+125°C; Tolerance: 10%; Voltage: 16V; Wattage: NA; Weight: 6mg; Datasheet: Y:\MIS_DATABASE\DATASHEETS\CAPACITORS\MURATA-GCM-SER.PDF
C19 = CAP: CAP CERAMIC 10uF 25V 20% X5R 0603; Chkd/date: MANIRAJA/040718; Crtd /date: MANIRAJA/040718; Custom_Duty: 15%; Customs_HS_Code: 85322990; Direct Alternate_mfr_name: SAMSUNG; Direct Alternate_mfr_part_number: CL10X106MO8NRNC; Distributor_name: DIGIKEY; Distributor_part_number: 490-10991-1-ND; Footprint Path: Y:\MIS_DATABASE\Library\ALTIUM_TOOL\PCB_FOOTPRINTS\Altium_Footprint_Lib.PcbLib; Height: 1.20MM; Library Path: Y:\MIS_DATABASE\Library\ALTIUM_TOOL\SCHEMATICS_PARTS\MS_DISCRETE_Library.schlib; Manufacturer: MURATA; Mfr_name: MURATA; Mfr_part_number: ZRB18AR61E106ME01L; Mistral Part No: 120018070001-R; Package: 0603; Part_type: CAPACITORS\CERAMIC; Project: CABS_VME_DIO; RoHS: RoHS; Temperature: -55°C+85°C; Tolerance: 20%; Voltage: 25V; Wattage: NA; Weight: 2mg; Datasheet: Y:\MIS_DATABASE\DATASHEETS\CAPACITORS\ZRB18AR61E106ME01L.PDF
J10 = CON_PMC_20X2_F_DP_TI: CON PMC 2X20 0.50MM PITCH FEMALE ST SMD; Chkd/date: MANIRAJA/251018; Crtd /date: ALVY/251018; Custom_Duty: 24%; Customs_HS_Code: 85369090; Distributor_name: DIGIKEY; Distributor_part_number: SAM10648-ND; Footprint Path: Y:\MIS_DATABASE\Library\ALTIUM_TOOL\PCB_FOOTPRINTS\Altium_Footprint_Lib.PcbLib; Height: 3.33MM; Library Path: Y:\MIS_DATABASE\Library\ALTIUM_TOOL\SCHEMATICS_PARTS\MS_CONNECTOR_Library.schlib; Library Ref: CON_PMC_20X2_F_DP; Manufacturer: SAMTEC; Mfr_name: SAMTEC; Mfr_part_number: QSH-020-01-L-D-DP-A-K; Mistral Part No: 150018100049-R; Package: SMD; Part_type: CONNECTOR\PMC; Project: TI_J7ES_EVM_CP; RoHS: RoHS; Temperature: -55°C+125°C; Tolerance: NA; Voltage: NA; Wattage: NA; Weight: NA; Datasheet: Y:\MIS_DATABASE\DATASHEETS\CONNECTORS\QSH-SERIES.PDF
R12 = RESISTOR: RES 0E 1/10W JUMPER 0402; Chkd/date: VASANTHA/061216; Crtd /date: NAVEED/201014; Custom_Duty: 15%; Customs_HS_Code: 85332119; Distributor_name: DIGIKEY; Distributor_part_number: P0.0JCT-ND; Footprint Path: Y:\MIS_DATABASE\Library\ALTIUM_TOOL\PCB_FOOTPRINTS\Altium_Footprint_Lib.PcbLib; Height: 0.40MM; IBISSP_MODLES: VALUE REPEATING 2 TIME; Library Path: Y:\MIS_DATABASE\Library\ALTIUM_TOOL\SCHEMATICS_PARTS\MS_DISCRETE_Library.schlib; Manufacturer: PANASONIC-ECG; Mfr_name: PANASONIC-ECG; Mfr_part_number: ERJ-2GE0R00X; Mistral Part No: 110018030052-R; Package: 0402; Part_type: RESISTORS\FIXED; Project: AEGIS POM; RoHS: RoHS; Temperature: -55°C+155°C; Tolerance: NA; Voltage: NA; Wattage: 1/10W; Weight: 0.8mg; Datasheet: Y:\MIS_DATABASE\DATASHEETS\RESISTORS\PAN-ERJSER_NOV17.PDF

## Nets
DGND: C12.2 C19.2 C68.2 C69.2 C70.2 C193.2 C203.2 C206.2 C207.2 C208.2 C209.2 C210.2 C211.2 C212.2 C213.2 C214.2 C215.2 C220.2 C224.2 C225.2 C231.2 C233.2 C237.2 C241.2 C242.2 C243.2 C244.2 C285.2 C349.2 C350.2 C351.2 C362.2 C363.2 C364.2 C383.2 C384.2 C385.2 C870.2 C873.2 C874.2 C875.2 C881.2 C887.2 C888.2 C889.2 C894.2 C895.2 C904.2 C916.2 C920.2 C922.2 C930.2 C943.2 C944.2 C959.2 C960.2 C971.2 C972.2 C984.2 C990.2 C995.2 C996.2 C999.2 C1003.2 C1005.2 C1008.2 C1012.2 C1026.2 C1031.2 C1036.2 C1290.2 C1291.2 C1292.2 C1293.2 C2582.2 C2583.2 C2584.2 C2585.2 C2586.2 C2587.2 C2588.2 C2589.2 C2590.2 C2591.2 C2592.2 FL43.2 FL43.4 FL44.2 FL44.4 FL45.2 FL45.4 FL46.2 FL46.4 FL122.2 FL122.4 FL137.2 FL137.4 FL141.2 FL141.4 FL150.2 FL150.4 FL154.2 FL154.4 FL170.2 FL170.4 FL177.2 FL177.4 FL193.2 FL193.4 J10.6 J10.12 J10.16 J10.24 J10.SH1 J10.SH2 J10.SH3 J10.SH4 TP21.1(TP) TP77.1(TP) TP95.1(TP) TP184.1(TP) TP192.1(TP) TP205.1(TP) U59.A1(VSS) U59.A4(VSS) U59.A7(VSS) U59.A23(VSS) U59.A25(VSS) U59.A27(VSS) U59.A29(VSS) U59.A31(VSS) U59.AA2(VSS) U59.AA5(VSS) U59.AA9(VSS) U59.AA11(VSS) U59.AA13(VSS) U59.AA15(VSS) U59.AA17(VSS) U59.AA19(VSS) U59.AA21(VSS) U59.AA23(VSS) U59.AA25(VSS) U59.AA27(VSS) U59.AA29(VSS) U59.AA31(VSS) U59.AA33(VSS) U59.AB1(VSS) U59.AB4(VSS) U59.AB8(VSS) U59.AB10(VSS) U59.AB12(VSS) U59.AB14(VSS) U59.AB18(VSS) U59.AB20(VSS) U59.AB22(VSS) U59.AB24(VSS) U59.AB26(VSS) U59.AB28(VSS) U59.AB30(VSS) U59.AB32(VSS) U59.AC2(VSS) U59.AC5(VSS) U59.AC9(VSS) U59.AC13(VSS) U59.AC15(VSS) U59.AC17(VSS) U59.AC19(VSS) U59.AC21(VSS) U59.AC23(VSS) U59.AC25(VSS) U59.AC27(VSS) U59.AD3(VSS) U59.AD6(VSS) U59.AD8(VSS) U59.AD10(VSS) U59.AD12(VSS) U59.AD14(VSS) U59.AD18(VSS) U59.AD22(VSS) U59.AD24(VSS) U59.AD26(VSS) U59.AD28(VSS) U59.AD29(VSS) U59.AD31(VSS) U59.AD33(VSS) U59.AE1(VSS) U59.AE4(VSS) U59.AE7(VSS) U59.AE13(VSS) U59.AE17(VSS) U59.AE19(VSS) U59.AE21(VSS) U59.AE23(VSS) U59.AE25(VSS) U59.AE27(VSS) U59.AE30(VSS) U59.AE32(VSS) U59.AF2(VSS) U59.AF5(VSS) U59.AF8(VSS) U59.AF11(VSS) U59.AF14(VSS) U59.AF18(VSS) U59.AF20(VSS) U59.AF21(VSS) U59.AF24(VSS) U59.AF28(VSS) U59.AG3(VSS) U59.AG6(VSS) U59.AG9(VSS) U59.AG14(VSS) U59.AG18(VSS) U59.AG20(VSS) U59.AG25(VSS) U59.AG28(VSS) U59.AG29(VSS) U59.AG31(VSS) U59.AG33(VSS) U59.AH5(VSS) U59.AH12(VSS) U59.AH15(VSS) U59.AH18(VSS) U59.AH21(VSS) U59.AH24(VSS) U59.AH26(VSS) U59.AH28(VSS) U59.AH30(VSS) U59.AJ6(VSS) U59.AJ8(VSS) U59.AJ11(VSS) U59.AJ14(VSS) U59.AJ17(VSS) U59.AJ20(VSS) U59.AJ23(VSS) U59.AJ26(VSS) U59.AJ29(VSS) U59.AJ32(VSS) U59.AK4(VSS) U59.AK7(VSS) U59.AK10(VSS) U59.AK13(VSS) U59.AK16(VSS) U59.AK19(VSS) U59.AK22(VSS) U59.AK25(VSS) U59.AK28(VSS) U59.AK31(VSS) U59.AL3(VSS) U59.AL6(VSS) U59.AL9(VSS) U59.AL12(VSS) U59.AL15(VSS) U59.AL18(VSS) U59.AL21(VSS) U59.AL24(VSS) U59.AL27(VSS) U59.AL30(VSS) U59.AL33(VSS) U59.AM2(VSS) U59.AM5(VSS) U59.AM8(VSS) U59.AM11(VSS) U59.AM14(VSS) U59.AM17(VSS) U59.AM20(VSS) U59.AM23(VSS) U59.AM26(VSS) U59.AM29(VSS) U59.AM32(VSS) U59.AM33(VSS) U59.AN1(VSS) U59.AN4(VSS) U59.AN7(VSS) U59.AN10(VSS) U59.AN13(VSS) U59.AN16(VSS) U59.AN19(VSS) U59.AN22(VSS) U59.AN25(VSS) U59.AN28(VSS) U59.AN31(VSS) U59.AN32(VSS) U59.B3(VSS) U59.B6(VSS) U59.B22(VSS) U59.B24(VSS) U59.B26(VSS) U59.B28(VSS) U59.B30(VSS) U59.B32(VSS) U59.C2(VSS) U59.C5(VSS) U59.C11(VSS) U59.C13(VSS) U59.C15(VSS) U59.C17(VSS) U59.C21(VSS) U59.C23(VSS) U59.C25(VSS) U59.C27(VSS) U59.C29(VSS) U59.C31(VSS) U59.C33(VSS) U59.D1(VSS) U59.D4(VSS) U59.D7(VSS) U59.D26(VSS) U59.D28(VSS) U59.D30(VSS) U59.D32(VSS) U59.E3(VSS) U59.E6(VSS) U59.E8(VSS) U59.E23(VSS) U59.E25(VSS) U59.E27(VSS) U59.E29(VSS) U59.E31(VSS) U59.F2(VSS) U59.F5(VSS) U59.F7(VSS) U59.F14(VSS) U59.F16(VSS) U59.F18(VSS) U59.F20(VSS) U59.F22(VSS) U59.F24(VSS) U59.G1(VSS) U59.G4(VSS) U59.G9(VSS) U59.G11(VSS) U59.G13(VSS) U59.G15(VSS) U59.G17(VSS) U59.G19(VSS) U59.G21(VSS) U59.G23(VSS) U59.G25(VSS) U59.G27(VSS) U59.H2(VSS) U59.H5(VSS) U59.H8(VSS) U59.H10(VSS) U59.H12(VSS) U59.H14(VSS) U59.H16(VSS) U59.H18(VSS) U59.H20(VSS) U59.H22(VSS) U59.H24(VSS) U59.H26(VSS) U59.H28(VSS) U59.J1(VSS) U59.J6(VSS) U59.J7(VSS) U59.J9(VSS) U59.J13(VSS) U59.J15(VSS) U59.J17(VSS) U59.J19(VSS) U59.J21(VSS) U59.K2(VSS) U59.K5(VSS) U59.K8(VSS) U59.K12(VSS) U59.K14(VSS) U59.K16(VSS) U59.K18(VSS) U59.K20(VSS) U59.K22(VSS) U59.K27(VSS) U59.K29(VSS) U59.L3(VSS) U59.L6(VSS) U59.L7(VSS) U59.L9(VSS) U59.L11(VSS) U59.L13(VSS) U59.L15(VSS) U59.L17(VSS) U59.L19(VSS) U59.L23(VSS) U59.M1(VSS) U59.M4(VSS) U59.M8(VSS) U59.M12(VSS) U59.M14(VSS) U59.M16(VSS) U59.M18(VSS) U59.M20(VSS) U59.M22(VSS) U59.M24(VSS) U59.M28(VSS) U59.N2(VSS) U59.N5(VSS) U59.N7(VSS) U59.N9(VSS) U59.N11(VSS) U59.N13(VSS) U59.N15(VSS) U59.N17(VSS) U59.N21(VSS) U59.N23(VSS) U59.N25(VSS) U59.N29(VSS) U59.P3(VSS) U59.P10(VSS) U59.P12(VSS) U59.P14(VSS) U59.P16(VSS) U59.P18(VSS) U59.P20(VSS) U59.P22(VSS) U59.P24(VSS) U59.P26(VSS) U59.R3(VSS) U59.R6(VSS) U59.R9(VSS) U59.R11(VSS) U59.R17(VSS) U59.R19(VSS) U59.R21(VSS) U59.R23(VSS) U59.R25(VSS) U59.R28(VSS) U59.T2(VSS) U59.T5(VSS) U59.T8(VSS) U59.T10(VSS) U59.T18(VSS) U59.T20(VSS) U59.T22(VSS) U59.T24(VSS) U59.T26(VSS) U59.U1(VSS) U59.U4(VSS) U59.U7(VSS) U59.U9(VSS) U59.U11(VSS) U59.U17(VSS) U59.U23(VSS) U59.U25(VSS) U59.U27(VSS) U59.U29(VSS) U59.U33(VSS) U59.V3(VSS) U59.V6(VSS) U59.V8(VSS) U59.V10(VSS) U59.V12(VSS) U59.V18(VSS) U59.V20(VSS) U59.V22(VSS) U59.V28(VSS) U59.W2(VSS) U59.W5(VSS) U59.W9(VSS) U59.W11(VSS) U59.W17(VSS) U59.W19(VSS) U59.W23(VSS) U59.W27(VSS) U59.W29(VSS) U59.Y1(VSS) U59.Y6(VSS) U59.Y8(VSS) U59.Y10(VSS) U59.Y12(VSS) U59.Y18(VSS) U59.Y20(VSS) U59.Y22(VSS) U59.Y26(VSS) U59.Y28(VSS) U5028.2 U5028.4 U5029.2 U5029.4 U5030.2 U5030.4 U5031.2 U5031.4 U5036.2 U5036.4 U5037.2 U5037.4 U5038.2 U5038.4 U5039.2 U5039.4 U5064.2 U5064.4 U5072.2 U5072.4 U5073.2 U5073.4 U5074.2 U5074.4 U5075.2 U5075.4 U5077.2 U5077.4 U5078.2 U5078.4 U5079.2 U5079.4 U5080.2 U5080.4 U5090.2 U5090.4 U5091.2 U5091.4 U5092.2 U5092.4 U5093.2 U5093.4 U5099.2 U5099.4 U50100.2 U50100.4 U50101.2 U50101.4 U50102.2 U50102.4 U50103.2 U50103.4 U50104.2 U50104.4 U50105.2 U50105.4 U50106.2 U50106.4 U50107.2 U50107.4 U50108.2 U50108.4 U50109.2 U50109.4 U50110.2 U50110.4 U50111.2 U50111.4 U50112.2 U50112.4 U50113.2 U50113.4 U50114.2 U50114.4 U50115.2 U50115.4 U50116.2 U50116.4 U50117.2 U50117.4 U50118.2 U50118.4 U50119.2 U50119.4 U50120.2 U50120.4 U50121.2 U50121.4 U50123.2 U50123.4 U50124.2 U50124.4 U50125.2 U50125.4 U50126.2 U50126.4 U50127.2 U50127.4 U50128.2 U50128.4 U50129.2 U50129.4 U50130.2 U50130.4 U50131.2 U50131.4 U50133.2 U50133.4 U50134.2 U50134.4 U50135.2 U50135.4 U50136.2 U50136.4 U50138.2 U50138.4 U50139.2 U50139.4 U50140.2 U50140.4 U50142.2 U50142.4 U50143.2 U50143.4 U50144.2 U50144.4 U50145.2 U50145.4 U50146.2 U50146.4 U50147.2 U50147.4 U50148.2 U50148.4 U50149.2 U50149.4 U50152.2 U50152.4 U50153.2 U50153.4 U50156.2 U50156.4 U50157.2 U50157.4 U50158.2 U50158.4 U50159.2 U50159.4 U50160.2 U50160.4 U50162.2 U50162.4 U50164.2 U50164.4 U50165.2 U50165.4 U50166.2 U50166.4 U50167.2 U50167.4 U50168.2 U50168.4 U50171.2 U50171.4 U50172.2 U50172.4 U50174.2 U50174.4 U50178.2 U50178.4 U50179.2 U50179.4 U50191.2 U50191.4 U50192.2 U50192.4 ; also on sheet 11 12 13 14 15 16 17 18 20 21 22 23 24 25 26 30 31 32 33 34 35 36 37 38 39 40 41 42 43 44 45 46 47 48 49 50 51 52 53 54 55 56 57 58 59 60 61 62 63 64 65 66 67 68 69 70 71 72 73 76 77 78 79 81 82 83 84
VDD_CORE_0V8: C193.1 C203.1 C220.1 C225.1 C237.1 C243.1 C995.1 C1008.1 C1290.1 C1291.1 C2586.1 C2587.1 C2588.1 C2589.1 C2590.1 C2591.1 C2592.1 R266.1 TP70.1(TP) U59.AA24(VDD_CORE) U59.AA26(VDD_CORE) U59.AA28(VDD_CORE) U59.AB23(VDD_CORE) U59.AB25(VDD_CORE) U59.AB27(VDD_CORE) U59.AC22(VDD_CORE) U59.AC24(VDD_CORE) U59.AC26(VDD_CORE) U59.AC28(VDD_CORE) U59.AD11(VDD_CORE) U59.AD15(VDD_CORE) U59.AD17(VDD_CORE) U59.AD21(VDD_CORE) U59.AD23(VDD_CORE) U59.AD25(VDD_CORE) U59.AD27(VDD_CORE) U59.AE10(VDD_CORE) U59.AE12(VDD_CORE) U59.AE14(VDD_CORE) U59.AE16(VDD_CORE) U59.AE18(VDD_CORE) U59.AE20(VDD_CORE) U59.AE22(VDD_CORE) U59.AE24(VDD_CORE) U59.AE28(VDD_CORE) U59.AF19(VDD_CORE) U59.K9(VDD_CORE) U59.K11(VDD_CORE) U59.K15(VDD_CORE) U59.K17(VDD_CORE) U59.L10(VDD_CORE) U59.L12(VDD_CORE) U59.L14(VDD_CORE) U59.L16(VDD_CORE) U59.M9(VDD_CORE) U59.M11(VDD_CORE) U59.M13(VDD_CORE) U59.M15(VDD_CORE) U59.M17(VDD_CORE) U59.N10(VDD_CORE) U59.N12(VDD_CORE) U59.N14(VDD_CORE) U59.N16(VDD_CORE) U59.N22(VDD_CORE) U59.N24(VDD_CORE) U59.N26(VDD_CORE) U59.P9(VDD_CORE) U59.P11(VDD_CORE) U59.P25(VDD_CORE) U59.R10(VDD_CORE) U59.R22(VDD_CORE) U59.R24(VDD_CORE) U59.R26(VDD_CORE) U59.T23(VDD_CORE) U59.T25(VDD_CORE) U59.U22(VDD_CORE) U59.U24(VDD_CORE) U59.U26(VDD_CORE) U59.U28(VDD_CORE) U59.V23(VDD_CORE) U59.V27(VDD_CORE) U59.W22(VDD_CORE) U59.W24(VDD_CORE) U59.W26(VDD_CORE) U59.W28(VDD_CORE) U59.Y23(VDD_CORE) U59.Y27(VDD_CORE) U5036.1 U5036.3 U5037.1 U5037.3 U5038.1 U5038.3 U5039.1 U5039.3 U5064.1 U5064.3 U5072.1 U5072.3 U5073.1 U5073.3 U5074.1 U5074.3 U5075.1 U5075.3 U5077.1 U5077.3 U5078.1 U5078.3 U5079.1 U5079.3 U5080.1 U5080.3 U5099.1 U5099.3 U50100.1 U50100.3 U50101.1 U50101.3 U50102.1 U50102.3 U50103.1 U50103.3 U50104.1 U50104.3 U50105.1 U50105.3 U50107.1 U50107.3 U50108.1 U50108.3 U50109.1 U50109.3 U50114.1 U50114.3 U50116.1 U50116.3 U50118.1 U50118.3 U50121.1 U50121.3 U50124.1 U50124.3 U50128.1 U50128.3 U50131.1 U50131.3 U50136.1 U50136.3 U50139.1 U50139.3 U50140.1 U50140.3 U50147.1 U50147.3 U50148.1 U50148.3 U50156.1 U50156.3 U50157.1 U50157.3 U50159.1 U50159.3 U50162.1 U50162.3 U50164.1 U50164.3 U50165.1 U50165.3 U50166.1 U50166.3 U50167.1 U50167.3 U50171.1 U50171.3 U50172.1 U50172.3 U50174.1 U50174.3 ; also on sheet 26 54 71 74
VDD_CPU_AVS: C206.1 C207.1 C208.1 C209.1 C210.1 C211.1 C212.1 C213.1 C214.1 C215.1 C922.1 C944.1 C996.1 C1292.1 C1293.1 C2582.1 C2583.1 C2584.1 C2585.1 R93.1 TP22.1(TP) U59.AA8(VDD_CPU) U59.AA10(VDD_CPU) U59.AA12(VDD_CPU) U59.AA20(VDD_CPU) U59.AB9(VDD_CPU) U59.AB11(VDD_CPU) U59.AB13(VDD_CPU) U59.AB15(VDD_CPU) U59.AB17(VDD_CPU) U59.AB19(VDD_CPU) U59.AB21(VDD_CPU) U59.AC8(VDD_CPU) U59.AC12(VDD_CPU) U59.AC14(VDD_CPU) U59.AC16(VDD_CPU) U59.AC18(VDD_CPU) U59.AC20(VDD_CPU) U59.AD9(VDD_CPU) U59.H19(VDD_CPU) U59.H21(VDD_CPU) U59.J18(VDD_CPU) U59.J20(VDD_CPU) U59.L18(VDD_CPU) U59.L20(VDD_CPU) U59.M19(VDD_CPU) U59.N18(VDD_CPU) U59.N20(VDD_CPU) U59.P15(VDD_CPU) U59.P17(VDD_CPU) U59.P19(VDD_CPU) U59.P21(VDD_CPU) U59.R12(VDD_CPU) U59.R20(VDD_CPU) U59.T9(VDD_CPU) U59.T11(VDD_CPU) U59.T17(VDD_CPU) U59.T19(VDD_CPU) U59.T21(VDD_CPU) U59.U8(VDD_CPU) U59.U10(VDD_CPU) U59.U18(VDD_CPU) U59.U20(VDD_CPU) U59.V11(VDD_CPU) U59.V19(VDD_CPU) U59.V21(VDD_CPU) U59.W8(VDD_CPU) U59.W10(VDD_CPU) U59.W12(VDD_CPU) U59.W18(VDD_CPU) U59.W20(VDD_CPU) U59.Y9(VDD_CPU) U59.Y17(VDD_CPU) U59.Y19(VDD_CPU) U59.Y21(VDD_CPU) U5028.1 U5028.3 U5029.1 U5029.3 U5030.1 U5030.3 U5031.1 U5031.3 U5090.1 U5090.3 U5091.1 U5091.3 U5092.1 U5092.3 U5093.1 U5093.3 U50106.1 U50106.3 U50110.1 U50110.3 U50111.1 U50111.3 U50112.1 U50112.3 U50113.1 U50113.3 U50115.1 U50115.3 U50117.1 U50117.3 U50119.1 U50119.3 U50120.1 U50120.3 U50123.1 U50123.3 U50125.1 U50125.3 U50126.1 U50126.3 U50127.1 U50127.3 U50129.1 U50129.3 U50130.1 U50130.3 U50133.1 U50133.3 U50134.1 U50134.3 U50135.1 U50135.3 U50138.1 U50138.3 U50142.1 U50142.3 U50143.1 U50143.3 U50144.1 U50144.3 U50145.1 U50145.3 U50146.1 U50146.3 U50149.1 U50149.3 U50152.1 U50152.3 U50153.1 U50153.3 U50158.1 U50158.3 U50160.1 U50160.3 U50168.1 U50168.3 U50178.1 U50178.3 U50179.1 U50179.3 U50191.1 U50191.3 U50192.1 U50192.3 ; also on sheet 22 54 70 74
VDD_DDR_1V1: R544.1 TP183.1(TP) ; also on sheet 14 15 26 69 74 75
VDD_MCU_0V85: C971.1 C972.1 C999.1 FL43.1 FL43.3 FL44.1 FL44.3 FL45.1 FL45.3 FL46.1 FL46.3 FL170.1 FL170.3 FL177.1 FL177.3 R580.1 TP204.1(TP) U59.J22(VDD_MCU) U59.K21(VDD_MCU) U59.K23(VDD_MCU) U59.L24(VDD_MCU) U59.M21(VDD_MCU) U59.M23(VDD_MCU) U59.M25(VDD_MCU) ; also on sheet 26 54 69 72 74
VDD_MCU_RAM_0V85: FL42.1 ; also on sheet 74
VDD_MCU_WAKE1: C1012.1 U59.J26(VDD_MCU_WAKE1) ; also on sheet 26
VDD_RAM_0V85: FL151.1 FL194.1 ; also on sheet 69 74
VDD_WAKE0: C943.1 U59.R27(VDD_WAKE0) ; also on sheet 26
VDDAR_CORE_0V85: C870.1 C873.1 C874.1 C875.1 C889.1 C894.1 C920.1 C930.1 C960.1 FL150.1 FL150.3 FL151.2 R556.1 TP191.1(TP) U59.AA22(VDDAR_CORE) U59.AD13(VDDAR_CORE) U59.AD16(VDDAR_CORE) U59.AD19(VDDAR_CORE) U59.AE9(VDDAR_CORE) U59.AE26(VDDAR_CORE) U59.P23(VDDAR_CORE) U59.Y25(VDDAR_CORE)
VDDAR_CPU_0V85: C881.1 C887.1 C888.1 C895.1 C904.1 C916.1 C959.1 C990.1 C1003.1 C1026.1 C1031.1 FL122.1 FL122.3 FL137.1 FL137.3 FL141.1 FL141.3 FL154.1 FL154.3 FL193.1 FL193.3 FL194.2 R323.1 TP99.1(TP) U59.AA14(VDDAR_CPU) U59.AA16(VDDAR_CPU) U59.AA18(VDDAR_CPU) U59.AC10(VDDAR_CPU) U59.K19(VDDAR_CPU) U59.L21(VDDAR_CPU) U59.P13(VDDAR_CPU) U59.R18(VDDAR_CPU) U59.U12(VDDAR_CPU) U59.U19(VDDAR_CPU) U59.V9(VDDAR_CPU) U59.V17(VDDAR_CPU) U59.Y11(VDDAR_CPU)
VDDAR_MCU_0V85: C285.1 C984.1 C1005.1 C1036.1 FL42.2 U59.K25(VDDAR_MCU) U59.L22(VDDAR_MCU)
CON_HYP0_RXFLCLK: J10.27 ; also on sheet 19
CON_HYP0_RXFLDAT: J10.25 ; also on sheet 19
CON_HYP0_RXPMCLK: J10.39 ; also on sheet 19
CON_HYP0_RXPMDAT: J10.37 ; also on sheet 19
CON_HYP0_TXFLCLK: J10.29 ; also on sheet 19
CON_HYP0_TXFLDAT: J10.31 ; also on sheet 19
CON_HYP0_TXPMCLK: J10.33 ; also on sheet 19
CON_HYP0_TXPMDAT: J10.35 ; also on sheet 19
CSI1_TX0_N: J10.11 ; also on sheet 11
CSI1_TX0_P: J10.9 ; also on sheet 11
CSI1_TX1_N: J10.15 ; also on sheet 11
CSI1_TX1_P: J10.13 ; also on sheet 11
CSI1_TX2_N: J10.19 ; also on sheet 11
CSI1_TX2_P: J10.17 ; also on sheet 11
CSI1_TX3_N: J10.23 ; also on sheet 11
CSI1_TX3_P: J10.21 ; also on sheet 11
CSI1_TXCLK_N: J10.7 ; also on sheet 11
CSI1_TXCLK_P: J10.5 ; also on sheet 11
HYP1_RXFLCLK: J10.20 ; also on sheet 20
HYP1_RXFLDAT: J10.22 ; also on sheet 20
HYP1_RXPMCLK: J10.8 ; also on sheet 20
HYP1_RXPMDAT: J10.10 ; also on sheet 20
HYP1_TXFLCLK: J10.18 ; also on sheet 20
HYP1_TXFLDAT: J10.14 ; also on sheet 20
HYP1_TXPMCLK: J10.4 ; also on sheet 20
HYP1_TXPMDAT: J10.2 ; also on sheet 20
VSYS_IO_3V3: C12.1 C19.1 R12.2 ; also on sheet 18 20 22 24 30 31 32 33 35 36 37 38 40 41 42 43 45 46 48 50 51 53 56 57 58 59 60 61 65 66 68 75 81 82
N33138535: J10.30 J10.32 J10.34 J10.36 J10.38 J10.40 R12.1
N34917262: C224.1 C231.1 C233.1 R266.2
N34917338: C68.1 C69.1 C70.1 R93.2
N34917376: C349.1 C350.1 C351.1 R544.2
N34917412: C383.1 C384.1 C385.1 R580.2
N34917448: C362.1 C363.1 C364.1 R556.2
N34917484: C241.1 C242.1 C244.1 R323.2

Not connected (* = marked no-connect by the designer): J10 1* 3* 26* 28*

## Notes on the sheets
sheet 27
- DIGITAL POWER 3
- Note:
  ------------------
  A few Dcaps shown here have been provisioned on PCB layout underneath SoC at
  individualpower ball vias & around perimeter in case additional high-freq decoupling
  might be needed.
  Some Dcaps may be shown as "Do Not Install" (DNI) components if Power Integrity (PI)
  simulation results for a particular power rail on this EVM PCB design combined with
  Dcap scheme (value, pkg type, ESL, Loop-Inductance, etc.) results in an impedance
  response below or equal to the desired target impedance (Zt).
sheet 28
- SOC GROUND
- SoC Supply Noise Kelvin Sensing
- Route supply & Gnd connections
  from SoC PoL as a pseudo
  differential pair to TPs near
  R & C termination for easy
  access
sheet 29
- HYPERLINK SIDEBAND CONNECTOR
- Reserved for 12V
- Hyperlink1
  Sideband Interface
- CSI-TX Interface
- Hyperlink0
  Sideband Interface
- silkscreen:"CSI-TX CONN"
